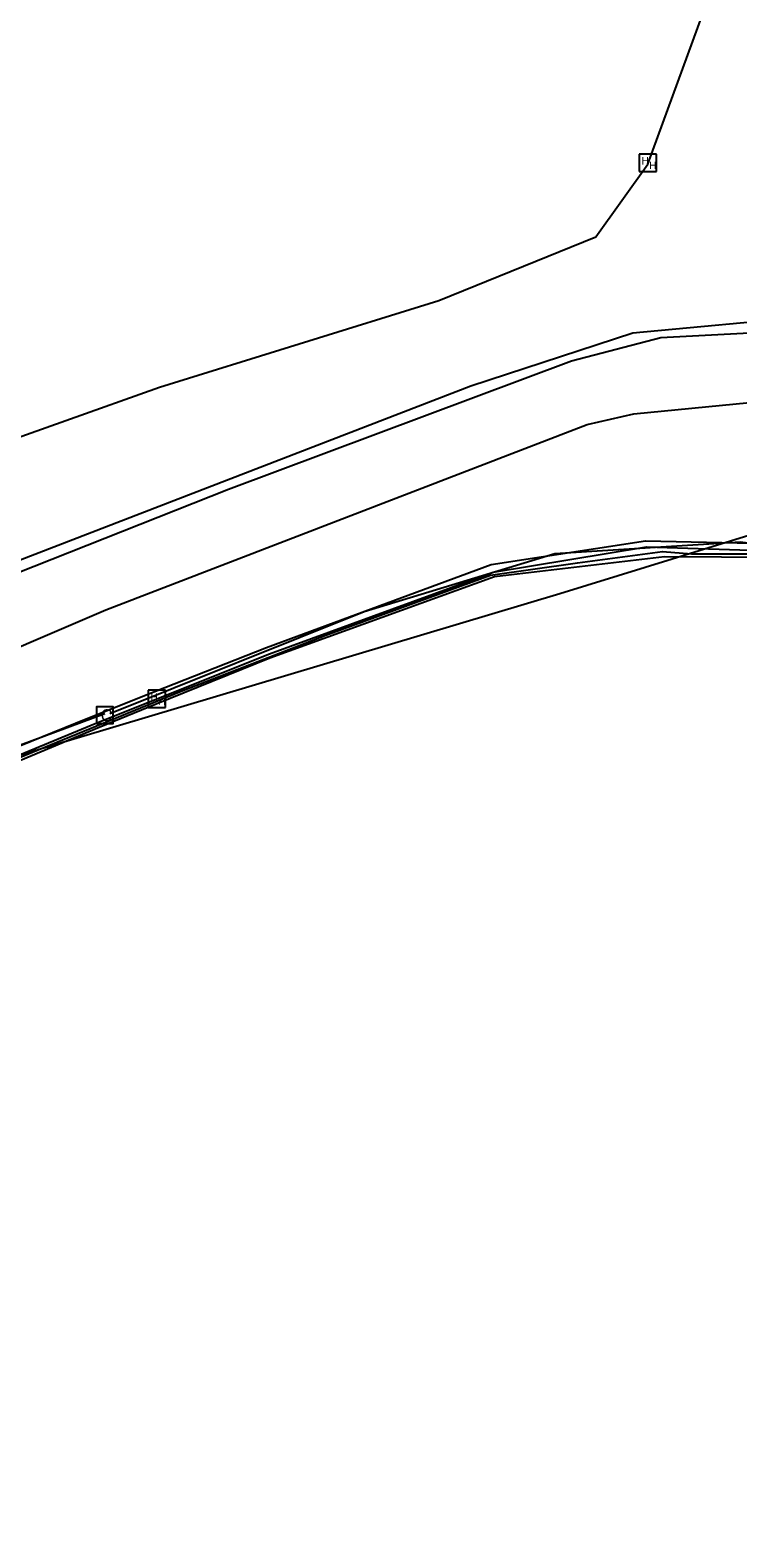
# Model space of a CAD drawing. Extents: x 2070721 to 2083340, y 729290 to 737883.
# Drawn here: x 2081411 to 2081646, y 734630 to 735132 of the extents above; entities that cross this region are included whole.
import ezdxf

# ---------------------------------------------------------------- set-up
doc = ezdxf.new("R2010")
doc.units = 0
for name, color, linetype in [('Exist Utilities Power UG Cable SUE LOS B', 7, 'Continuous'), ('Exist Utilities Power UG Cable SUE LOS C', 7, 'Continuous'), ('Exist Utilities Telephone Hand Hole CELL', 7, 'Continuous'), ('Exist Utilities Telephone UG Cable SUE LOS C', 7, 'Continuous'), ('Exist Utilities Telephone UG FO SUE LOS B', 7, 'Continuous'), ('Exist Utilities TV Pedestal CELL', 7, 'Continuous'), ('Exist Utilities TV UG Cable SUE LOS B', 7, 'Continuous'), ('Exist Utilities TV UG FO Cable SUE LOS B', 7, 'Continuous'), ('Exist Utilities Water UG Line SUE LOS B', 7, 'Continuous')]:
    doc.layers.add(name, color=color, linetype=linetype)

msp = doc.modelspace()

# ---------------------------------------------------------------- linework, layer by layer
at = {"layer": 'Exist Utilities Power UG Cable SUE LOS B'}
msp.add_lwpolyline([(2081128.97, 734740.08), (2081231.48, 734798.66), (2081295.17, 734834.12), (2081365.43, 734871.31), (2081433.71, 734899.92), (2081452.63, 734907.74), (2081490.45, 734923.08), (2081565.19, 734950.13), (2081621.73, 734956.73), (2081659.71, 734956.5), (2081779.27, 734939), (2081838.04, 734926)], dxfattribs=at)
at = {"layer": 'Exist Utilities Power UG Cable SUE LOS C'}
for points in [[(2080186.05, 734475.29), (2080187.03, 734475.63), (2080448.94, 734565.1), (2080663.08, 734641.37), (2080827.26, 734699.95), (2080984.4, 734756.05), (2081109.44, 734801.16), (2081210.88, 734831.9), (2081586.98, 734944.46), (2081830.55, 735019.69), (2082038.54, 735143.44), (2082248.34, 735270.09)], [(2081398.46, 734886.3), (2081460.49, 734911.77), (2081509.14, 734930.55), (2081563.83, 734950.54), (2081592.79, 734954.64), (2081621.06, 734958.42), (2081630.74, 734957.65), (2081639.48, 734957.65), (2081657.7, 734957.65), (2081672.52, 734956.07), (2081771.45, 734941.91), (2081817.43, 734931.74), (2081831.08, 734932.73), (2081838.68, 734936.87), (2081850.29, 734958.08), (2081862.4, 734995.7), (2081864.93, 735002.95)]]:
    msp.add_lwpolyline(points, dxfattribs=at)
at = {"layer": 'Exist Utilities Telephone Hand Hole CELL'}
for p, q in [((2081613.33, 735090.67), (2081613.33, 735084.95)), ((2081619.05, 735090.67), (2081613.33, 735090.67)), ((2081619.05, 735084.95), (2081619.05, 735090.67)), ((2081616.19, 735087.81), (2081616.19, 735087.81)), ((2081613.33, 735084.95), (2081619.05, 735084.95)), ((2081450.05, 734912.23), (2081450.05, 734906.51)), ((2081455.77, 734912.23), (2081450.05, 734912.23)), ((2081455.77, 734906.51), (2081455.77, 734912.23)), ((2081450.05, 734906.51), (2081455.77, 734906.51)), ((2081452.91, 734909.37), (2081452.91, 734909.37))]:
    msp.add_line(p, q, dxfattribs=at)
at = {"layer": 'Exist Utilities Telephone UG Cable SUE LOS C'}
for points in [[(2080527.18, 734594.58), (2080756.63, 734677.7), (2080975.53, 734755.33), (2081114.85, 734806.49), (2081251.31, 734880.3), (2081357.91, 734934.96), (2081407.46, 734955.63), (2081557.34, 735013.56), (2081611.19, 735031.21), (2081670.8, 735036.79), (2081727.82, 735033.26), (2081796.62, 735020.83), (2081876.61, 734998.57), (2081913.61, 734982.12), (2081940.08, 734960.79), (2081955.36, 734908.6), (2081940.34, 734844.38), (2081917.15, 734795.51)], [(2080934.26, 734720.97), (2081041, 734761.39), (2081061.56, 734773.15), (2081150.65, 734813.71), (2081201.33, 734846.96), (2081300.64, 734903.05), (2081400.2, 734948.86), (2081476.71, 734979.23), (2081590.79, 735021.91), (2081620.53, 735029.68), (2081685.91, 735033.08), (2081745.92, 735027.46), (2081824.22, 735009.88), (2081875.43, 734995.15), (2081909.49, 734979.28), (2081909.49, 734966.35), (2081906.46, 734953.04)]]:
    msp.add_lwpolyline(points, dxfattribs=at)
at = {"layer": 'Exist Utilities Telephone UG FO SUE LOS B'}
for points in [[(2080939.09, 734839.81), (2081012.97, 734869.95), (2081083.01, 734898.2), (2081127.31, 734908.53), (2081225.25, 734938.31), (2081315.55, 734966.89), (2081391.31, 734990.94), (2081453.77, 735013.11), (2081546.69, 735041.99), (2081598.87, 735063.2), (2081616.23, 735087.34), (2081634.46, 735137.35), (2081640.11, 735152.98), (2081692.01, 735167.85), (2081764.85, 735199.16), (2081820.69, 735222.51), (2081887.44, 735259.15), (2081965.65, 735305.42), (2082025.06, 735334.79), (2082065.42, 735359.68), (2082065.33, 735359.8), (2082125.22, 735390.95)], [(2081099.85, 734724.62), (2081112.42, 734732.94), (2081128.56, 734742.73), (2081231.52, 734800.87), (2081294.72, 734835.92), (2081365.04, 734873.38), (2081431.01, 734900.6), (2081452.87, 734909.38), (2081490.35, 734924.36), (2081564.77, 734951.57), (2081615.8, 734959.97), (2081660.54, 734958.55), (2081778.72, 734942.12), (2081841.31, 734922.44), (2081868.96, 734908.94)]]:
    msp.add_lwpolyline(points, dxfattribs=at)
at = {"layer": 'Exist Utilities TV Pedestal CELL'}
msp.add_line((2081435.56, 734903.92), (2081435.56, 734903.92), dxfattribs=at)
msp.add_lwpolyline([(2081432.79, 734901.15), (2081438.33, 734901.15), (2081438.33, 734906.7), (2081432.79, 734906.7), (2081432.79, 734901.15)], dxfattribs=at)
at = {"layer": 'Exist Utilities TV UG Cable SUE LOS B'}
for points in [[(2081437.24, 734904.54), (2081521.81, 734938.42), (2081585.32, 734957.8), (2081647.07, 734961.7), (2081778.73, 734943.71)], [(2081119.77, 734739.04), (2081129.13, 734744.58), (2081197.49, 734782.76), (2081230.42, 734801.16), (2081319.02, 734852.15), (2081394.96, 734889.39), (2081435.57, 734904.49)]]:
    msp.add_lwpolyline(points, dxfattribs=at)
at = {"layer": 'Exist Utilities TV UG FO Cable SUE LOS B'}
msp.add_lwpolyline([(2081119.77, 734739.04), (2081129.02, 734745.24), (2081193.81, 734780.91), (2081230.47, 734802.17), (2081292.91, 734838.4), (2081363.18, 734875.86), (2081429.44, 734902.7), (2081451.9, 734911.7), (2081489.36, 734926.43), (2081564.05, 734954.16), (2081615.43, 734961.96), (2081661.12, 734960.94), (2081779.14, 734944.37)], dxfattribs=at)
at = {"layer": 'Exist Utilities Water UG Line SUE LOS B'}
msp.add_lwpolyline([(2080902.52, 734692.58), (2081024.44, 734735.33), (2081064.65, 734749.07), (2081167.38, 734801.25), (2081288.56, 734870.47), (2081329.8, 734893.5), (2081435.94, 734938.99), (2081596, 735000.71), (2081611.53, 735004.3), (2081650.19, 735007.99), (2081750.43, 735003.6), (2081775.33, 734999.48), (2081852.16, 734980.94), (2081900.97, 734962.81), (2081973.29, 734925.34), (2081993.87, 734913.23), (2081994.94, 734912.69)], dxfattribs=at)

# ---------------------------------------------------------------- texts
at = {"layer": 'Exist Utilities Telephone Hand Hole CELL'}
for p in [(2081614.11, 735087.22), (2081616.68, 735085.75), (2081450.83, 734908.78), (2081453.4, 734907.31)]:
    msp.add_text('H', height=2.5, dxfattribs=at).set_placement(p)
at = {"layer": 'Exist Utilities TV Pedestal CELL'}
msp.add_text('C', height=4, dxfattribs=at).set_placement((2081434.25, 734901.92))

doc.saveas('drawing.dxf')
